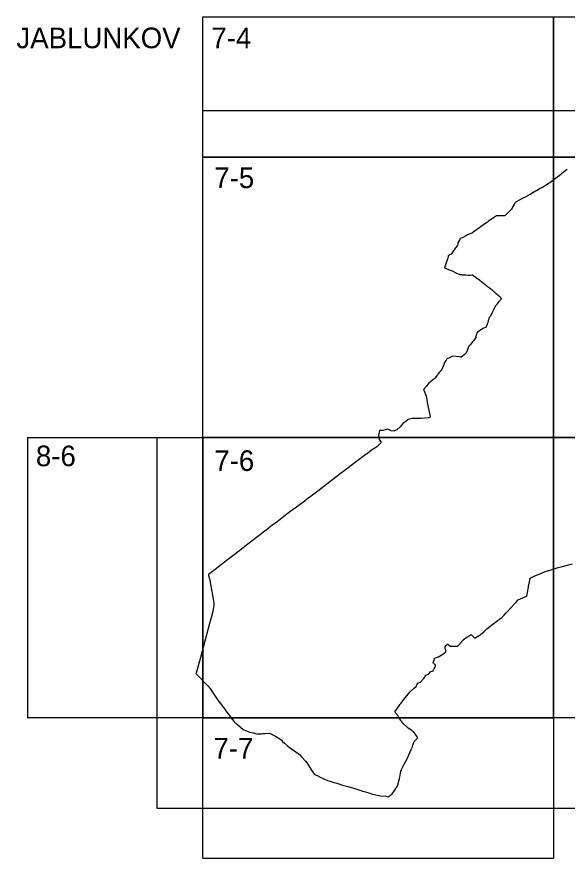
# Model space of a CAD drawing. Extents: x -447352 to -425530, y -1135906 to -1125104.
# Drawn here: x -431751.9 to -431506.7, y -1126653.4 to -1126278.4 of the extents above; entities that cross this region are included whole.
import ezdxf

# ---------------------------------------------------------------- set-up
doc = ezdxf.new("R2010")
doc.units = 0
for name, color, linetype in [('Vrstva 1', 7, 'Continuous'), ('Vrstva 10', 7, 'Continuous'), ('Vrstva 4', 7, 'Continuous')]:
    doc.layers.add(name, color=color, linetype=linetype)

msp = doc.modelspace()

# ---------------------------------------------------------------- linework, layer by layer
at = {"layer": 'Vrstva 1'}
for points in [[(-431506.66, -1126346.44), (-431507.87, -1126347.4), (-431507.87, -1126347.4), (-431509.02, -1126348.27), (-431509.59, -1126348.7), (-431510.17, -1126349.14), (-431510.33, -1126349.26), (-431512.46, -1126350.9), (-431513.53, -1126351.72), (-431514, -1126352.06), (-431514.76, -1126352.57), (-431515.01, -1126352.73), (-431515.6, -1126353.12), (-431515.64, -1126353.15), (-431515.85, -1126353.29), (-431516.76, -1126353.89), (-431516.77, -1126353.89), (-431517.24, -1126354.15), (-431517.39, -1126354.23), (-431517.57, -1126354.33), (-431518.03, -1126354.58), (-431518.21, -1126354.69), (-431518.37, -1126354.78), (-431518.47, -1126354.84), (-431518.71, -1126354.98), (-431520.37, -1126355.92), (-431520.54, -1126356.01), (-431520.77, -1126356.14), (-431523.24, -1126357.54), (-431523.36, -1126357.61), (-431525.47, -1126358.74), (-431526.49, -1126359.29), (-431529.83, -1126361.1), (-431530, -1126361.4), (-431530.06, -1126361.51), (-431530.84, -1126362.97), (-431531.52, -1126364.29), (-431531.66, -1126364.42), (-431531.75, -1126364.5), (-431532.89, -1126365.54), (-431534.4, -1126366.92), (-431534.57, -1126367.07), (-431534.57, -1126367.08), (-431535.04, -1126367.09), (-431538.23, -1126367.18), (-431538.24, -1126367.18), (-431538.67, -1126367.47), (-431539.5, -1126368.04), (-431541.97, -1126369.7), (-431542.01, -1126369.72), (-431542.25, -1126369.9), (-431542.52, -1126370.1), (-431545.5, -1126372.23), (-431545.57, -1126372.28), (-431548.57, -1126374.46), (-431549.04, -1126374.8), (-431549.2, -1126374.86), (-431551.14, -1126375.58), (-431551.15, -1126375.58), (-431551.54, -1126375.82), (-431553.42, -1126376.98), (-431554.34, -1126377.19), (-431554.59, -1126377.7), (-431555.35, -1126379.21), (-431555.36, -1126379.22), (-431555.43, -1126379.48), (-431555.63, -1126380.32), (-431556.46, -1126381.43), (-431557.83, -1126383.38), (-431558.39, -1126384.19), (-431558.42, -1126384.21), (-431559.58, -1126384.85), (-431559.68, -1126384.91), (-431559.75, -1126385.3), (-431559.9, -1126386.11), (-431559.95, -1126386.3), (-431561.24, -1126389.88), (-431561.41, -1126390.36), (-431561.38, -1126390.35), (-431561.36, -1126390.34), (-431560.68, -1126390.6), (-431558.87, -1126391.26), (-431558.25, -1126391.55), (-431555.96, -1126392.63), (-431555.94, -1126392.63), (-431554.78, -1126393.1), (-431554.31, -1126393.28), (-431554.28, -1126393.29), (-431553.85, -1126393.32), (-431553.71, -1126393.33), (-431553.49, -1126393.35), (-431551.89, -1126393.45), (-431550.85, -1126393.52), (-431549.8, -1126393.49), (-431548.96, -1126393.46), (-431548.95, -1126393.46), (-431548.67, -1126393.61), (-431548.3, -1126393.87), (-431547.75, -1126394.25), (-431547.36, -1126394.53), (-431545.8, -1126395.67), (-431545.63, -1126395.79), (-431544.52, -1126396.71), (-431544.13, -1126397.03), (-431543.95, -1126397.18), (-431543.2, -1126397.79), (-431542.93, -1126398.02), (-431542.33, -1126398.51), (-431542.11, -1126398.69), (-431541.47, -1126399.11), (-431540.72, -1126399.61), (-431540.69, -1126399.63), (-431539.93, -1126400.31), (-431539.05, -1126401.09), (-431538.61, -1126401.47), (-431537.6, -1126402.36), (-431537.34, -1126402.59), (-431537.29, -1126402.64), (-431537.19, -1126402.74), (-431537.18, -1126402.75), (-431537.09, -1126402.85), (-431537.06, -1126402.88), (-431536.01, -1126404.11), (-431536.02, -1126404.12), (-431536.46, -1126404.61), (-431536.52, -1126404.68), (-431537.09, -1126405.31), (-431537.91, -1126406.37), (-431538.08, -1126406.58), (-431538.64, -1126407.3), (-431538.94, -1126407.83), (-431538.96, -1126407.87), (-431538.97, -1126407.89), (-431539.1, -1126408.17), (-431539.9, -1126409.84), (-431540.21, -1126410.48), (-431540.83, -1126411.77), (-431540.94, -1126412.01), (-431540.95, -1126412.01), (-431540.99, -1126412.04), (-431541.28, -1126412.24), (-431541.36, -1126412.28), (-431541.41, -1126412.38), (-431541.5, -1126412.58), (-431541.59, -1126412.86), (-431541.76, -1126413.42), (-431541.77, -1126413.44), (-431541.89, -1126413.94), (-431541.91, -1126414.01), (-431541.9, -1126414.07), (-431541.89, -1126414.15), (-431541.89, -1126414.22), (-431541.9, -1126414.27), (-431542.78, -1126416.6), (-431542.8, -1126416.65), (-431542.82, -1126416.69), (-431542.83, -1126416.7), (-431543.53, -1126417), (-431543.78, -1126417.11), (-431544.25, -1126417.35), (-431546.86, -1126419.04), (-431546.86, -1126419.04), (-431547.23, -1126420.35), (-431547.31, -1126420.61), (-431547.42, -1126421.03), (-431547.48, -1126421.24), (-431547.48, -1126421.25), (-431547.47, -1126421.25), (-431547.3, -1126421.41), (-431547.31, -1126421.42), (-431547.67, -1126421.81), (-431548.47, -1126422.81), (-431548.48, -1126422.82), (-431548.69, -1126423.07), (-431548.69, -1126423.08), (-431548.81, -1126423.23), (-431549.97, -1126424.58), (-431550.51, -1126425.21), (-431551.27, -1126427.16), (-431551.65, -1126428.18), (-431551.78, -1126428.53), (-431553.31, -1126429.63), (-431553.93, -1126430.07), (-431554.11, -1126430.11), (-431554.13, -1126430.11), (-431554.76, -1126430.02), (-431557.6, -1126429.6), (-431558.09, -1126429.84), (-431559.42, -1126430.48), (-431559.96, -1126430.74), (-431559.99, -1126430.77), (-431560.42, -1126431.18), (-431560.59, -1126431.4), (-431561.25, -1126432.25), (-431561.25, -1126432.26), (-431561.92, -1126434.06), (-431562.49, -1126435.56), (-431562.49, -1126435.56), (-431562.63, -1126435.78), (-431562.96, -1126436.15), (-431563.68, -1126436.95), (-431564.38, -1126437.72), (-431564.39, -1126437.74), (-431564.52, -1126437.93), (-431565.59, -1126439.5), (-431566.06, -1126439.88), (-431567.63, -1126441.14), (-431568.3, -1126441.68), (-431568.4, -1126441.76), (-431568.43, -1126441.8), (-431569.55, -1126443.23), (-431570.69, -1126444.54), (-431570.54, -1126444.71), (-431570.53, -1126444.74), (-431570.53, -1126444.75), (-431569.52, -1126447.51), (-431569.24, -1126449.17), (-431568.92, -1126451.12), (-431568.51, -1126453.08), (-431567.78, -1126456.58), (-431567.74, -1126456.78), (-431568.39, -1126457.12), (-431568.51, -1126457.19), (-431571.68, -1126457.45), (-431571.84, -1126457.45), (-431573.33, -1126457.42), (-431575.72, -1126457.4), (-431577, -1126457.67), (-431577.6, -1126457.94), (-431578.58, -1126458.74), (-431579.88, -1126459.61), (-431579.97, -1126459.72), (-431581.13, -1126461.14), (-431582.58, -1126462.48), (-431583.27, -1126462.8), (-431583.87, -1126463.08), (-431585.04, -1126463.01), (-431586.65, -1126462.16), (-431588.89, -1126462.83), (-431590.37, -1126462.8), (-431590.75, -1126464.91), (-431590.76, -1126464.93), (-431590.77, -1126465.02), (-431590.48, -1126466.83), (-431589.51, -1126468.15), (-431589.5, -1126468.17), (-431590.24, -1126468.92), (-431590.85, -1126469.48), (-431591.1, -1126469.71), (-431591.9, -1126470.34), (-431593.83, -1126471.57), (-431593.89, -1126471.61), (-431595.86, -1126473.14), (-431595.92, -1126473.18), (-431596.41, -1126473.56), (-431601.07, -1126477.02), (-431601.1, -1126477.05), (-431606.05, -1126480.81), (-431610.31, -1126484.06), (-431611.19, -1126484.72), (-431613.76, -1126486.66), (-431617.76, -1126489.79), (-431620.2, -1126491.66), (-431623.51, -1126494.19), (-431623.56, -1126494.23), (-431628.35, -1126497.74), (-431628.58, -1126497.92), (-431632.19, -1126500.6), (-431634.58, -1126502.42), (-431636.55, -1126503.9), (-431638.87, -1126505.65), (-431639.1, -1126505.82), (-431640.23, -1126506.71), (-431645.05, -1126510.51), (-431648.94, -1126513.46), (-431653.16, -1126516.71), (-431654.45, -1126517.71), (-431656.84, -1126519.59), (-431658.02, -1126520.51), (-431661.96, -1126523.56), (-431662.89, -1126524.27), (-431664.13, -1126525.23), (-431666.45, -1126527.03), (-431666.45, -1126527.03), (-431666.41, -1126527.21), (-431666.12, -1126528.59), (-431666.09, -1126528.75), (-431665.56, -1126531.29), (-431665.4, -1126532.02), (-431665.4, -1126532.06), (-431664.47, -1126537.94), (-431664.46, -1126537.97), (-431664.16, -1126539.7), (-431664.16, -1126539.72), (-431664.1, -1126540.09), (-431664.04, -1126540.51), (-431664.07, -1126540.88), (-431664.22, -1126541.61), (-431664.6, -1126543.4), (-431664.89, -1126544.58), (-431664.91, -1126544.63), (-431666.02, -1126548.8), (-431668.12, -1126556.68), (-431670.11, -1126563.9), (-431672.04, -1126571), (-431672.05, -1126571.04), (-431666.77, -1126576.64), (-431665.72, -1126577.77), (-431664.96, -1126578.99), (-431662.94, -1126582.05), (-431662.89, -1126582.12), (-431661.88, -1126583.53), (-431661.72, -1126583.74), (-431659.84, -1126586.22), (-431659.27, -1126586.96), (-431659.24, -1126587), (-431658.72, -1126587.72), (-431657.34, -1126589.62), (-431657.01, -1126590.07), (-431654.86, -1126592.79), (-431653.46, -1126594.01), (-431651.06, -1126595.99), (-431649.32, -1126596.74), (-431648.13, -1126597.26), (-431648, -1126597.31), (-431646.67, -1126597.59), (-431646.53, -1126597.62), (-431644.91, -1126597.95), (-431644.88, -1126597.95), (-431643.92, -1126597.93), (-431643.54, -1126597.93), (-431643.02, -1126597.92), (-431642.34, -1126597.91), (-431641.43, -1126597.87), (-431639.48, -1126597.71), (-431639.03, -1126597.78), (-431638.37, -1126598.13), (-431636.65, -1126599.08), (-431634.69, -1126600.18), (-431634.17, -1126600.66), (-431633.45, -1126601.34), (-431632.65, -1126602.09), (-431631.33, -1126603.39), (-431631.19, -1126603.49), (-431630, -1126604.34), (-431627.59, -1126606.05), (-431625.95, -1126607.23), (-431624.9, -1126608.41), (-431623.26, -1126610.23), (-431622.62, -1126610.94), (-431622.26, -1126611.53), (-431621.8, -1126612.27), (-431620.86, -1126613.74), (-431620.23, -1126614.66), (-431619.19, -1126616.1), (-431618.12, -1126616.61), (-431616.74, -1126617.26), (-431615.43, -1126617.87), (-431613.46, -1126618.76), (-431612.33, -1126619.11), (-431610.61, -1126619.68), (-431610.46, -1126619.73), (-431609.37, -1126620.05), (-431607.95, -1126620.47), (-431607.94, -1126620.47), (-431607.73, -1126620.53), (-431607.67, -1126620.55), (-431606.81, -1126620.81), (-431604.42, -1126621.5), (-431604.3, -1126621.54), (-431603.82, -1126621.68), (-431600.89, -1126622.55), (-431598.2, -1126623.38), (-431597.86, -1126623.48), (-431597.1, -1126623.71), (-431595.09, -1126624.33), (-431593.36, -1126624.88), (-431589.9, -1126625.62)], [(-431589.9, -1126625.62), (-431587.51, -1126625.81), (-431586.31, -1126626.04), (-431586.2, -1126625.95), (-431584.62, -1126624.68), (-431583.59, -1126623.2), (-431583.48, -1126623.05), (-431582.96, -1126622.29), (-431582.85, -1126622.12), (-431582.71, -1126621.89), (-431582.33, -1126621.26), (-431582.06, -1126620.43), (-431582.04, -1126620.36), (-431582.02, -1126620.31), (-431581.99, -1126620.2), (-431581.96, -1126620.11), (-431581.96, -1126620.1), (-431581.33, -1126617.9), (-431581.19, -1126617.38), (-431580.74, -1126614.63), (-431580.74, -1126614.63), (-431580.55, -1126614.19), (-431580.29, -1126613.57), (-431579.5, -1126611.74), (-431577.93, -1126609.09), (-431576.18, -1126604.96), (-431575.86, -1126604.32), (-431575.82, -1126604.19), (-431575.43, -1126603.09), (-431574.84, -1126601.42), (-431573.16, -1126599.71), (-431574.09, -1126598.47), (-431574.15, -1126598.38), (-431574.2, -1126598.32), (-431574.23, -1126598.28), (-431574.3, -1126598.18), (-431574.35, -1126598.1), (-431574.43, -1126597.98), (-431574.79, -1126597.46), (-431575.16, -1126597), (-431575.73, -1126596.63), (-431575.83, -1126596.57), (-431577.48, -1126595.5), (-431579.67, -1126593.56), (-431579.8, -1126593.39), (-431579.83, -1126593.35), (-431579.91, -1126593.25), (-431580.25, -1126592.83), (-431580.58, -1126592.42), (-431580.84, -1126592.1), (-431581.32, -1126591.51), (-431581.4, -1126591.41), (-431581.9, -1126590.45), (-431582.19, -1126589.89), (-431582.42, -1126589.46), (-431582.47, -1126589.37), (-431582.51, -1126589.32), (-431582.77, -1126589.03), (-431582.97, -1126588.8), (-431583.23, -1126588.51), (-431583.45, -1126588.26), (-431581.59, -1126585.52), (-431581.5, -1126585.4), (-431581.18, -1126584.95), (-431580.86, -1126584.51), (-431579.53, -1126582.68), (-431576.85, -1126579.42), (-431576.5, -1126579.1), (-431575.79, -1126578.4), (-431575.68, -1126578.31), (-431575.49, -1126578.17), (-431574.89, -1126577.69), (-431574.03, -1126576.85), (-431573.62, -1126576.09), (-431573.15, -1126575.22), (-431572.1, -1126574.98), (-431570.7, -1126573.55), (-431570.16, -1126572.7), (-431570.15, -1126572.69), (-431570.15, -1126572.67), (-431569.94, -1126572.34), (-431569.89, -1126572.26), (-431569.65, -1126571.87), (-431568.49, -1126571.43), (-431567.47, -1126570.25), (-431566.94, -1126570.05), (-431566.82, -1126570), (-431566.4, -1126569.84), (-431566.18, -1126569.45), (-431566.13, -1126569.36), (-431565.96, -1126569.06), (-431565.55, -1126568.32), (-431565.35, -1126567.41), (-431565.35, -1126567.39), (-431565.34, -1126567.38), (-431566.39, -1126566.39), (-431566.41, -1126566.38), (-431566.42, -1126566.36), (-431566.47, -1126566.32), (-431565.82, -1126564.52), (-431565.75, -1126564.32), (-431565.59, -1126564.26), (-431564.86, -1126563.97), (-431564.17, -1126563.7), (-431564.05, -1126563.65), (-431562.84, -1126562.94), (-431562.72, -1126562.86), (-431562.72, -1126562.86), (-431562.71, -1126562.85), (-431562.59, -1126562.78), (-431560.73, -1126561.38), (-431560.73, -1126561.34), (-431560.76, -1126561.18), (-431560.83, -1126560.7), (-431560.89, -1126560.35), (-431560.99, -1126559.73), (-431561.01, -1126559.62), (-431561.03, -1126559.49), (-431561.05, -1126559.32), (-431561.08, -1126559.18), (-431560.54, -1126558.62), (-431559.98, -1126558.05), (-431559.94, -1126558), (-431559.8, -1126558.1), (-431558.8, -1126558.89), (-431558.12, -1126558.9), (-431558.06, -1126558.9), (-431557.81, -1126558.91), (-431557.65, -1126558.91), (-431556.34, -1126558.93), (-431555.71, -1126558.95), (-431555.44, -1126558.79), (-431555.41, -1126558.77), (-431555.29, -1126558.7), (-431555.15, -1126558.61), (-431555.11, -1126558.58), (-431554.57, -1126557.98), (-431554.46, -1126557.86), (-431554.37, -1126557.76), (-431554.2, -1126557.58), (-431554.12, -1126557.49), (-431554.01, -1126557.37), (-431553.98, -1126557.33), (-431553.95, -1126557.3), (-431553.9, -1126557.24), (-431553.81, -1126557.13), (-431553.41, -1126556.63), (-431553.2, -1126556.37), (-431552.95, -1126556.05), (-431552.84, -1126555.97), (-431551.38, -1126554.9), (-431551.17, -1126554.77), (-431549.81, -1126554), (-431549.41, -1126553.77), (-431549.41, -1126553.77), (-431549.27, -1126553.92), (-431548.56, -1126554.63), (-431548.19, -1126555.01), (-431548.01, -1126555.18), (-431547.86, -1126555.33), (-431547.77, -1126555.29), (-431546.49, -1126554.52), (-431546.4, -1126554.47), (-431545.47, -1126553.91), (-431545.43, -1126553.88), (-431545.1, -1126553.59), (-431545.05, -1126553.55), (-431544.88, -1126553.4), (-431544.87, -1126553.39), (-431544.87, -1126553.39), (-431544.83, -1126553.35), (-431544.79, -1126553.31), (-431543.9, -1126552.5), (-431543.88, -1126552.49), (-431543.29, -1126551.95), (-431543.18, -1126551.86), (-431543.07, -1126551.76), (-431543.07, -1126551.76), (-431543.06, -1126551.76), (-431543.06, -1126551.76), (-431543.06, -1126551.75), (-431543.05, -1126551.75), (-431543.04, -1126551.74), (-431543.04, -1126551.74), (-431543.03, -1126551.73), (-431543.03, -1126551.73), (-431543.02, -1126551.73), (-431543.02, -1126551.73), (-431542.44, -1126551.24), (-431540.45, -1126549.56), (-431539.25, -1126548.71), (-431539.13, -1126548.63), (-431539.08, -1126548.59), (-431539.06, -1126548.58), (-431539.01, -1126548.55), (-431538.65, -1126548.28), (-431537.41, -1126547.34), (-431537.23, -1126547.2), (-431537.02, -1126547.04), (-431537, -1126547.02), (-431536.12, -1126546.35), (-431535.77, -1126546.08), (-431535.72, -1126546.02), (-431535.63, -1126545.92), (-431534.99, -1126545.24), (-431534.09, -1126544.26), (-431532.73, -1126542.85), (-431532.51, -1126542.62), (-431532.26, -1126542.34), (-431531.42, -1126541.39), (-431531.13, -1126541.07), (-431530.93, -1126540.86), (-431530.64, -1126540.54), (-431529.46, -1126539.35), (-431528.53, -1126538.33), (-431526.47, -1126537.32), (-431526.31, -1126537.27), (-431526.11, -1126537.19), (-431524.67, -1126536.7), (-431524.52, -1126535.83), (-431524.36, -1126534.96), (-431523.94, -1126532.59), (-431523.86, -1126532.12), (-431523.53, -1126530.24), (-431523.33, -1126529.36), (-431523.3, -1126529.24), (-431523.25, -1126529.05), (-431523.24, -1126529.01), (-431523.22, -1126528.94), (-431523.21, -1126528.9), (-431523.2, -1126528.85), (-431523.19, -1126528.81), (-431523.18, -1126528.79), (-431523.12, -1126528.58), (-431522.04, -1126528.04), (-431521.75, -1126527.9), (-431521.73, -1126527.89), (-431521.48, -1126527.76), (-431521.43, -1126527.74), (-431519.66, -1126527.02), (-431519.63, -1126527.01), (-431519.6, -1126526.99), (-431518.8, -1126526.68), (-431517.84, -1126526.28), (-431517.03, -1126525.94), (-431516.09, -1126525.55), (-431516.01, -1126525.52), (-431515.4, -1126525.28), (-431515.55, -1126525.44), (-431515.31, -1126525.35), (-431514.82, -1126525.15), (-431514.29, -1126524.99), (-431512.59, -1126524.47), (-431512, -1126524.3), (-431511.55, -1126524.18), (-431510.66, -1126523.93), (-431509.35, -1126523.55), (-431507.81, -1126523.09), (-431504.27, -1126522.22)]]:
    msp.add_lwpolyline(points, dxfattribs=at)
at = {"layer": 'Vrstva 10'}
msp.add_lwpolyline([(-431356.51, -1126320.23), (-431356.51, -1126631.21), (-431689.38, -1126631.21), (-431689.38, -1126465.91), (-431669.01, -1126465.91), (-431669.01, -1126340.91), (-431669.01, -1126320.23), (-431356.51, -1126320.23)], dxfattribs=at)
at = {"layer": 'Vrstva 4'}
for p, q in [((-431669.01, -1126278.41), (-431356.51, -1126278.41)), ((-431747.14, -1126465.91), (-431747.14, -1126590.91)), ((-431669.01, -1126653.41), (-431512.76, -1126653.41))]:
    msp.add_line(p, q, dxfattribs=at)
for points in [[(-431512.76, -1126278.41), (-431512.76, -1126340.91), (-431669.01, -1126340.91), (-431669.01, -1126278.41)], [(-431356.51, -1126278.41), (-431356.51, -1126340.91), (-431512.76, -1126340.91), (-431512.76, -1126278.41)], [(-431747.14, -1126465.91), (-431669.01, -1126465.91), (-431669.01, -1126590.91), (-431747.14, -1126590.91)], [(-431669.01, -1126653.41), (-431669.01, -1126590.91), (-431512.76, -1126590.91), (-431512.76, -1126653.41)]]:
    msp.add_lwpolyline(points, dxfattribs=at)
for points in [[(-431512.76, -1126340.91), (-431512.76, -1126465.91), (-431669.01, -1126465.91), (-431669.01, -1126340.91)], [(-431356.51, -1126340.91), (-431356.51, -1126465.91), (-431512.76, -1126465.91), (-431512.76, -1126340.91)], [(-431512.76, -1126465.91), (-431512.76, -1126590.91), (-431669.01, -1126590.91), (-431669.01, -1126465.91)], [(-431356.51, -1126465.91), (-431356.51, -1126590.91), (-431512.76, -1126590.91), (-431512.76, -1126465.91)]]:
    msp.add_lwpolyline(points, close=True, dxfattribs=at)

# ---------------------------------------------------------------- texts
at = {"layer": 'Vrstva 1'}
for s, p in [('JABLUNKOV', (-431752.05, -1126292.41)), ('7-4', (-431665.2, -1126292.41)), ('7-5', (-431663.89, -1126354.75)), ('8-6', (-431743.36, -1126478.72)), ('7-6', (-431663.89, -1126480.82)), ('7-7', (-431664.25, -1126608.99))]:
    msp.add_text(s, height=9.2, dxfattribs=at).set_placement(p)

doc.saveas('drawing.dxf')
